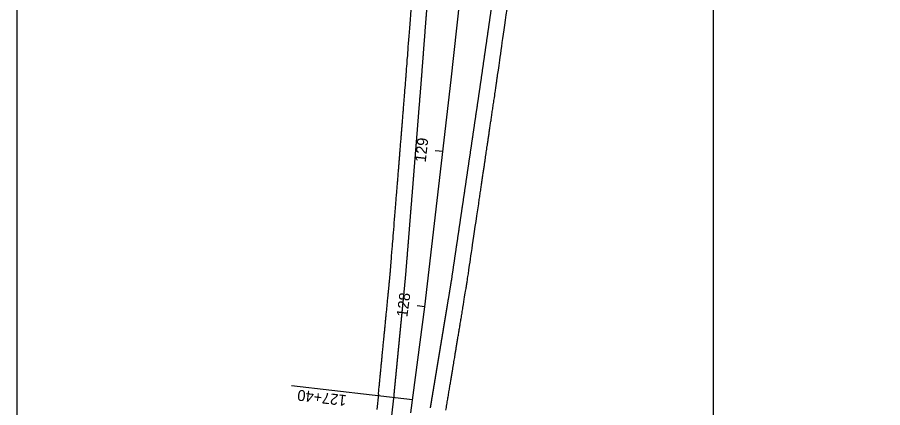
# Model space of a CAD drawing. Extents: x 2318076 to 2324211, y 613525 to 630327.
# Drawn here: x 2320224 to 2320778, y 627311 to 627561 of the extents above; entities that cross this region are included whole.
import ezdxf

# ---------------------------------------------------------------- set-up
doc = ezdxf.new("R2010")
doc.units = 0
for name, color, linetype in [('GE_P_CL_50', 7, 'Continuous'), ('PV_P_EOP', 7, 'Continuous'), ('PV_P_Shoulder', 7, 'Continuous'), ('SC_Scratch3', 7, 'Continuous')]:
    doc.layers.add(name, color=color, linetype=linetype)

msp = doc.modelspace()

# ---------------------------------------------------------------- linework, layer by layer
at = {"layer": 'GE_P_CL_50'}
for p, q in [((2320496.86, 627474.89), (2320491.9, 627475.45)), ((2320485.22, 627375.57), (2320480.26, 627376.22)), ((2320477.27, 627316.1), (2320399.9, 627325.01))]:
    msp.add_line(p, q, dxfattribs=at)
msp.add_lwpolyline([(2320476.3, 627307.7), (2320485.22, 627375.57), (2320502.11, 627520.92), (2320519.22, 627676.47), (2320531.82, 627783.89), (2320546.8, 627927.12), (2320554.45, 627991.34), (2320572.51, 628138.41), (2320649.52, 628804.84), (2320678.77, 629064.5), (2320690.76, 629163.78), (2320713.75, 629362.45), (2320725.26, 629461.78), (2320736.97, 629561.09), (2320748.4, 629660.43), (2320759.09, 629759.86), (2320769.62, 629859.3), (2320777.51, 629931.12), (2320778.25, 629937.84)], dxfattribs=at)
at = {"layer": 'PV_P_EOP'}
msp.add_lwpolyline([(2320449.32, 627178.38), (2320465.49, 627318.74)], dxfattribs=at)
for points in [[(2320482.44, 627513.23), (2320482.51, 627514.12), (2320482.59, 627515.02), (2320482.66, 627515.92), (2320482.73, 627516.82), (2320482.8, 627517.72), (2320482.88, 627518.62), (2320482.95, 627519.52), (2320483.02, 627520.41), (2320483.09, 627521.31), (2320483.16, 627522.21), (2320483.23, 627523.04), (2320483.3, 627523.94), (2320483.37, 627524.84), (2320483.43, 627525.73), (2320483.5, 627526.63), (2320483.57, 627527.53), (2320483.64, 627528.43), (2320483.71, 627529.33), (2320483.78, 627530.23), (2320483.85, 627531.13), (2320483.91, 627532.03), (2320483.98, 627532.92), (2320484.05, 627533.82), (2320484.12, 627534.72), (2320484.19, 627535.62), (2320484.26, 627536.52), (2320484.33, 627537.42), (2320484.4, 627538.32), (2320484.46, 627539.22), (2320484.53, 627540.11), (2320484.6, 627541.01), (2320484.67, 627541.91), (2320484.74, 627542.81), (2320484.81, 627543.71), (2320484.88, 627544.61), (2320484.94, 627545.51), (2320485.01, 627546.41), (2320485.08, 627547.31), (2320485.15, 627548.2), (2320485.22, 627549.1), (2320485.29, 627550), (2320485.36, 627550.9), (2320485.43, 627551.8), (2320485.49, 627552.7), (2320485.56, 627553.6), (2320485.63, 627554.5), (2320485.7, 627555.39), (2320485.77, 627556.29), (2320485.84, 627557.19), (2320485.91, 627558.09), (2320485.98, 627558.99), (2320486.04, 627559.89), (2320486.11, 627560.79), (2320486.18, 627561.69), (2320486.25, 627562.58), (2320486.32, 627563.48), (2320486.39, 627564.38), (2320486.46, 627565.28), (2320486.52, 627566.18), (2320486.59, 627567.08), (2320486.66, 627567.98), (2320486.73, 627568.88), (2320486.8, 627569.77), (2320486.87, 627570.67), (2320486.94, 627571.57), (2320487.01, 627572.47), (2320487.07, 627573.37), (2320487.14, 627574.27), (2320487.21, 627575.17), (2320487.28, 627576.07), (2320487.35, 627576.96), (2320487.42, 627577.86), (2320487.49, 627578.76), (2320487.56, 627579.66)], [(2320519.54, 627509), (2320519.67, 627509.89), (2320519.8, 627510.78), (2320519.93, 627511.68), (2320520.06, 627512.57), (2320520.2, 627513.46), (2320520.33, 627514.35), (2320520.46, 627515.24), (2320520.59, 627516.14), (2320520.72, 627517.03), (2320520.85, 627517.92), (2320520.99, 627518.88), (2320521.12, 627519.77), (2320521.25, 627520.67), (2320521.38, 627521.56), (2320521.51, 627522.45), (2320521.64, 627523.34), (2320521.76, 627524.24), (2320521.89, 627525.13), (2320522.02, 627526.02), (2320522.15, 627526.91), (2320522.28, 627527.8), (2320522.41, 627528.7), (2320522.53, 627529.59), (2320522.66, 627530.48), (2320522.79, 627531.37), (2320522.92, 627532.27), (2320523.05, 627533.16), (2320523.18, 627534.05), (2320523.3, 627534.94), (2320523.43, 627535.83), (2320523.56, 627536.73), (2320523.69, 627537.62), (2320523.82, 627538.51), (2320523.95, 627539.4), (2320524.08, 627540.3), (2320524.2, 627541.19), (2320524.33, 627542.08), (2320524.46, 627542.97), (2320524.59, 627543.86), (2320524.72, 627544.76), (2320524.85, 627545.65), (2320524.97, 627546.54), (2320525.1, 627547.43), (2320525.23, 627548.33), (2320525.36, 627549.22), (2320525.49, 627550.11), (2320525.62, 627551), (2320525.74, 627551.89), (2320525.87, 627552.79), (2320526, 627553.68), (2320526.13, 627554.57), (2320526.26, 627555.46), (2320526.39, 627556.36), (2320526.51, 627557.25), (2320526.64, 627558.14), (2320526.77, 627559.03), (2320526.9, 627559.92), (2320527.03, 627560.82), (2320527.16, 627561.71), (2320527.28, 627562.6), (2320527.41, 627563.49), (2320527.54, 627564.38), (2320527.67, 627565.28), (2320527.8, 627566.17), (2320527.93, 627567.06), (2320528.06, 627567.95), (2320528.18, 627568.85), (2320528.31, 627569.74), (2320528.44, 627570.63), (2320528.57, 627571.52), (2320528.7, 627572.41), (2320528.83, 627573.31), (2320528.95, 627574.2), (2320529.08, 627575.09)], [(2320477.11, 627446.74), (2320477.18, 627447.63), (2320477.25, 627448.53), (2320477.32, 627449.43), (2320477.39, 627450.33), (2320477.47, 627451.23), (2320477.54, 627452.13), (2320477.61, 627453.03), (2320477.68, 627453.92), (2320477.76, 627454.82), (2320477.83, 627455.72), (2320477.9, 627456.62), (2320477.97, 627457.52), (2320478.04, 627458.42), (2320478.12, 627459.32), (2320478.19, 627460.21), (2320478.26, 627461.11), (2320478.33, 627462.01), (2320478.4, 627462.91), (2320478.48, 627463.81), (2320478.55, 627464.71), (2320478.62, 627465.61), (2320478.69, 627466.5), (2320478.76, 627467.4), (2320478.84, 627468.3), (2320478.91, 627469.2), (2320478.98, 627470.1), (2320479.05, 627471), (2320479.13, 627471.89), (2320479.2, 627472.79), (2320479.27, 627473.69), (2320479.34, 627474.59), (2320479.41, 627475.49), (2320479.49, 627476.39), (2320479.56, 627477.29), (2320479.63, 627478.18), (2320479.7, 627479.08), (2320479.77, 627479.98), (2320479.85, 627480.88), (2320479.92, 627481.78), (2320479.99, 627482.68), (2320480.06, 627483.58), (2320480.13, 627484.47), (2320480.21, 627485.37), (2320480.28, 627486.27), (2320480.35, 627487.17), (2320480.42, 627488.07), (2320480.5, 627488.97), (2320480.57, 627489.87), (2320480.64, 627490.76), (2320480.71, 627491.66), (2320480.78, 627492.56), (2320480.86, 627493.46), (2320480.93, 627494.36), (2320481, 627495.26), (2320481.07, 627496.15), (2320481.14, 627497.05), (2320481.22, 627497.95), (2320481.29, 627498.85), (2320481.36, 627499.75), (2320481.43, 627500.65), (2320481.51, 627501.55), (2320481.58, 627502.44), (2320481.65, 627503.34), (2320481.72, 627504.24), (2320481.79, 627505.14), (2320481.87, 627506.04), (2320481.94, 627506.94), (2320482.01, 627507.84), (2320482.08, 627508.73), (2320482.15, 627509.63), (2320482.23, 627510.53), (2320482.3, 627511.43), (2320482.37, 627512.33), (2320482.44, 627513.23)], [(2320509.78, 627443.01), (2320509.92, 627443.91), (2320510.05, 627444.8), (2320510.18, 627445.69), (2320510.31, 627446.58), (2320510.44, 627447.47), (2320510.57, 627448.36), (2320510.71, 627449.26), (2320510.84, 627450.15), (2320510.97, 627451.04), (2320511.1, 627451.93), (2320511.23, 627452.82), (2320511.37, 627453.72), (2320511.5, 627454.61), (2320511.63, 627455.5), (2320511.76, 627456.39), (2320511.89, 627457.28), (2320512.02, 627458.17), (2320512.16, 627459.07), (2320512.29, 627459.96), (2320512.42, 627460.85), (2320512.55, 627461.74), (2320512.68, 627462.63), (2320512.81, 627463.52), (2320512.95, 627464.42), (2320513.08, 627465.31), (2320513.21, 627466.2), (2320513.34, 627467.09), (2320513.47, 627467.98), (2320513.61, 627468.87), (2320513.74, 627469.77), (2320513.87, 627470.66), (2320514, 627471.55), (2320514.13, 627472.44), (2320514.26, 627473.33), (2320514.4, 627474.22), (2320514.53, 627475.12), (2320514.66, 627476.01), (2320514.79, 627476.9), (2320514.92, 627477.79), (2320515.06, 627478.68), (2320515.19, 627479.57), (2320515.32, 627480.47), (2320515.45, 627481.36), (2320515.58, 627482.25), (2320515.71, 627483.14), (2320515.85, 627484.03), (2320515.98, 627484.93), (2320516.11, 627485.82), (2320516.24, 627486.71), (2320516.37, 627487.6), (2320516.5, 627488.49), (2320516.64, 627489.38), (2320516.77, 627490.28), (2320516.9, 627491.17), (2320517.03, 627492.06), (2320517.16, 627492.95), (2320517.3, 627493.84), (2320517.43, 627494.73), (2320517.56, 627495.63), (2320517.69, 627496.52), (2320517.82, 627497.41), (2320517.95, 627498.3), (2320518.09, 627499.19), (2320518.22, 627500.08), (2320518.35, 627500.98), (2320518.48, 627501.87), (2320518.61, 627502.76), (2320518.75, 627503.65), (2320518.88, 627504.54), (2320519.01, 627505.43), (2320519.14, 627506.33), (2320519.27, 627507.22), (2320519.4, 627508.11), (2320519.54, 627509)], [(2320471.53, 627380.52), (2320471.62, 627381.42), (2320471.7, 627382.32), (2320471.79, 627383.22), (2320471.88, 627384.11), (2320471.97, 627385.01), (2320472.05, 627385.91), (2320472.14, 627386.8), (2320472.23, 627387.7), (2320472.32, 627388.6), (2320472.4, 627389.5), (2320472.49, 627390.39), (2320472.58, 627391.29), (2320472.67, 627392.19), (2320472.75, 627393.08), (2320472.84, 627393.98), (2320472.93, 627394.88), (2320473.02, 627395.78), (2320473.07, 627396.42), (2320473.14, 627397.32), (2320473.21, 627398.22), (2320473.28, 627399.12), (2320473.36, 627400.01), (2320473.43, 627400.91), (2320473.5, 627401.81), (2320473.57, 627402.71), (2320473.64, 627403.61), (2320473.72, 627404.51), (2320473.79, 627405.4), (2320473.86, 627406.3), (2320473.93, 627407.2), (2320474.01, 627408.1), (2320474.08, 627409), (2320474.15, 627409.9), (2320474.22, 627410.8), (2320474.29, 627411.69), (2320474.37, 627412.59), (2320474.44, 627413.49), (2320474.51, 627414.39), (2320474.58, 627415.29), (2320474.65, 627416.19), (2320474.73, 627417.09), (2320474.8, 627417.98), (2320474.87, 627418.88), (2320474.94, 627419.78), (2320475.01, 627420.68), (2320475.09, 627421.58), (2320475.16, 627422.48), (2320475.23, 627423.38), (2320475.3, 627424.27), (2320475.38, 627425.17), (2320475.45, 627426.07), (2320475.52, 627426.97), (2320475.59, 627427.87), (2320475.66, 627428.77), (2320475.74, 627429.66), (2320475.81, 627430.56), (2320475.88, 627431.46), (2320475.95, 627432.36), (2320476.02, 627433.26), (2320476.1, 627434.16), (2320476.17, 627435.06), (2320476.24, 627435.95), (2320476.31, 627436.85), (2320476.38, 627437.75), (2320476.46, 627438.65), (2320476.53, 627439.55), (2320476.6, 627440.45), (2320476.67, 627441.35), (2320476.75, 627442.24), (2320476.82, 627443.14), (2320476.89, 627444.04), (2320476.96, 627444.94), (2320477.03, 627445.84), (2320477.11, 627446.74)], [(2320499.73, 627376.82), (2320499.88, 627377.71), (2320500.02, 627378.6), (2320500.17, 627379.48), (2320500.32, 627380.37), (2320500.47, 627381.26), (2320500.61, 627382.15), (2320500.76, 627383.04), (2320500.91, 627383.93), (2320501.05, 627384.82), (2320501.2, 627385.71), (2320501.35, 627386.6), (2320501.5, 627387.49), (2320501.64, 627388.38), (2320501.79, 627389.27), (2320501.94, 627390.16), (2320502.08, 627391.05), (2320502.23, 627391.93), (2320502.4, 627393.08), (2320502.54, 627393.97), (2320502.67, 627394.86), (2320502.8, 627395.75), (2320502.93, 627396.65), (2320503.06, 627397.54), (2320503.19, 627398.43), (2320503.33, 627399.32), (2320503.46, 627400.21), (2320503.59, 627401.1), (2320503.72, 627402), (2320503.85, 627402.89), (2320503.98, 627403.78), (2320504.12, 627404.67), (2320504.25, 627405.56), (2320504.38, 627406.45), (2320504.51, 627407.35), (2320504.64, 627408.24), (2320504.78, 627409.13), (2320504.91, 627410.02), (2320505.04, 627410.91), (2320505.17, 627411.8), (2320505.3, 627412.7), (2320505.43, 627413.59), (2320505.57, 627414.48), (2320505.7, 627415.37), (2320505.83, 627416.26), (2320505.96, 627417.15), (2320506.09, 627418.05), (2320506.23, 627418.94), (2320506.36, 627419.83), (2320506.49, 627420.72), (2320506.62, 627421.61), (2320506.75, 627422.51), (2320506.88, 627423.4), (2320507.02, 627424.29), (2320507.15, 627425.18), (2320507.28, 627426.07), (2320507.41, 627426.96), (2320507.54, 627427.86), (2320507.68, 627428.75), (2320507.81, 627429.64), (2320507.94, 627430.53), (2320508.07, 627431.42), (2320508.2, 627432.31), (2320508.33, 627433.21), (2320508.47, 627434.1), (2320508.6, 627434.99), (2320508.73, 627435.88), (2320508.86, 627436.77), (2320508.99, 627437.66), (2320509.12, 627438.56), (2320509.26, 627439.45), (2320509.39, 627440.34), (2320509.52, 627441.23), (2320509.65, 627442.12), (2320509.78, 627443.01)]]:
    msp.add_spline(points, degree=3, dxfattribs=at)
for points in [[(2320465.49, 627318.73), (2320465.52, 627318.99), (2320465.54, 627319.25), (2320465.57, 627319.52), (2320465.6, 627319.82), (2320465.63, 627320.12), (2320465.66, 627320.42), (2320465.69, 627320.72), (2320465.71, 627321.01), (2320465.74, 627321.31), (2320465.77, 627321.61), (2320465.8, 627321.91), (2320465.83, 627322.21), (2320465.86, 627322.51), (2320465.89, 627322.81), (2320465.92, 627323.11), (2320465.95, 627323.41), (2320465.98, 627323.71), (2320466.01, 627324), (2320466.04, 627324.3), (2320466.07, 627324.6), (2320466.09, 627324.9), (2320466.12, 627325.2), (2320466.15, 627325.5), (2320466.18, 627325.8), (2320466.21, 627326.1), (2320466.24, 627326.4), (2320466.27, 627326.7), (2320466.3, 627327), (2320466.33, 627327.29), (2320466.36, 627327.59), (2320466.39, 627327.89), (2320466.42, 627328.19), (2320466.45, 627328.49), (2320466.47, 627328.79), (2320466.5, 627329.09), (2320466.53, 627329.39), (2320466.56, 627329.69), (2320466.59, 627329.99), (2320466.62, 627330.28), (2320466.65, 627330.58), (2320466.68, 627330.88), (2320466.71, 627331.18), (2320466.74, 627331.48), (2320466.77, 627331.78), (2320466.8, 627332.08), (2320466.82, 627332.38), (2320466.85, 627332.68), (2320466.88, 627332.98), (2320466.91, 627333.28), (2320466.94, 627333.57), (2320466.97, 627333.87), (2320467, 627334.17), (2320467.03, 627334.47), (2320467.06, 627334.77), (2320467.09, 627335.07), (2320467.12, 627335.37), (2320467.15, 627335.67), (2320467.18, 627335.97), (2320467.2, 627336.27), (2320467.23, 627336.56), (2320467.26, 627336.86), (2320467.29, 627337.16), (2320467.32, 627337.46), (2320467.35, 627337.76), (2320467.38, 627338.06), (2320467.41, 627338.36), (2320467.44, 627338.66), (2320467.47, 627338.96), (2320467.5, 627339.26), (2320467.53, 627339.55), (2320467.56, 627339.85), (2320467.58, 627340.15), (2320467.61, 627340.45), (2320467.64, 627340.75), (2320467.67, 627341.05), (2320467.7, 627341.35), (2320467.73, 627341.65), (2320467.76, 627341.95), (2320467.79, 627342.25), (2320467.82, 627342.55), (2320467.85, 627342.84), (2320467.88, 627343.14), (2320467.91, 627343.44), (2320467.93, 627343.74), (2320467.96, 627344.04), (2320467.99, 627344.34), (2320468.02, 627344.64), (2320468.05, 627344.94), (2320468.08, 627345.24), (2320468.11, 627345.54), (2320468.14, 627345.83), (2320468.17, 627346.13), (2320468.2, 627346.43), (2320468.23, 627346.73), (2320468.26, 627347.03), (2320468.29, 627347.33), (2320468.31, 627347.63), (2320468.34, 627347.93), (2320468.37, 627348.23), (2320468.4, 627348.53), (2320468.43, 627348.83), (2320468.46, 627349.12), (2320468.49, 627349.42), (2320468.52, 627349.72), (2320468.55, 627350.02), (2320468.58, 627350.32), (2320468.61, 627350.62), (2320468.64, 627350.92), (2320468.67, 627351.22), (2320468.69, 627351.52), (2320468.72, 627351.82), (2320468.75, 627352.11), (2320468.78, 627352.41), (2320468.81, 627352.71), (2320468.84, 627353.01), (2320468.87, 627353.31), (2320468.9, 627353.61), (2320468.93, 627353.91), (2320468.96, 627354.21), (2320468.99, 627354.51), (2320469.02, 627354.81), (2320469.04, 627355.11), (2320469.07, 627355.4), (2320469.1, 627355.7), (2320469.13, 627356), (2320469.16, 627356.3), (2320469.19, 627356.6), (2320469.22, 627356.9), (2320469.25, 627357.2), (2320469.28, 627357.5), (2320469.31, 627357.8), (2320469.34, 627358.1), (2320469.37, 627358.39), (2320469.4, 627358.69), (2320469.42, 627358.99), (2320469.45, 627359.29), (2320469.48, 627359.59), (2320469.51, 627359.89), (2320469.54, 627360.19), (2320469.57, 627360.49), (2320469.6, 627360.79), (2320469.63, 627361.09), (2320469.66, 627361.39), (2320469.69, 627361.68), (2320469.72, 627361.98), (2320469.75, 627362.28), (2320469.78, 627362.58), (2320469.8, 627362.88), (2320469.83, 627363.18), (2320469.86, 627363.48), (2320469.89, 627363.78), (2320469.92, 627364.08), (2320469.95, 627364.38), (2320469.98, 627364.67), (2320470.01, 627364.97), (2320470.04, 627365.27), (2320470.07, 627365.57), (2320470.1, 627365.87), (2320470.13, 627366.17), (2320470.16, 627366.47), (2320470.18, 627366.77), (2320470.21, 627367.07), (2320470.24, 627367.37), (2320470.27, 627367.67), (2320470.3, 627367.96), (2320470.33, 627368.26), (2320470.36, 627368.56), (2320470.39, 627368.86), (2320470.42, 627369.16), (2320470.45, 627369.46), (2320470.48, 627369.76), (2320470.51, 627370.06), (2320470.53, 627370.36), (2320470.56, 627370.66), (2320470.59, 627370.95), (2320470.62, 627371.25), (2320470.65, 627371.55), (2320470.68, 627371.85), (2320470.71, 627372.15), (2320470.74, 627372.45), (2320470.77, 627372.75), (2320470.8, 627373.05), (2320470.83, 627373.35), (2320470.86, 627373.65), (2320470.89, 627373.94), (2320470.91, 627374.24), (2320470.94, 627374.54), (2320470.97, 627374.84), (2320471, 627375.14), (2320471.03, 627375.44), (2320471.06, 627375.74), (2320471.09, 627376.04), (2320471.12, 627376.34), (2320471.15, 627376.64), (2320471.18, 627376.94), (2320471.21, 627377.23), (2320471.24, 627377.53), (2320471.27, 627377.83), (2320471.29, 627378.13), (2320471.32, 627378.43), (2320471.35, 627378.73), (2320471.38, 627379.03), (2320471.41, 627379.33), (2320471.44, 627379.63), (2320471.47, 627379.93), (2320471.5, 627380.22), (2320471.53, 627380.52)], [(2320488.84, 627311.01), (2320488.89, 627311.3), (2320488.94, 627311.6), (2320488.99, 627311.9), (2320489.03, 627312.19), (2320489.08, 627312.49), (2320489.13, 627312.79), (2320489.18, 627313.08), (2320489.23, 627313.38), (2320489.28, 627313.68), (2320489.33, 627313.97), (2320489.38, 627314.27), (2320489.43, 627314.57), (2320489.48, 627314.86), (2320489.52, 627315.16), (2320489.57, 627315.45), (2320489.62, 627315.75), (2320489.67, 627316.05), (2320489.72, 627316.34), (2320489.77, 627316.64), (2320489.82, 627316.94), (2320489.87, 627317.23), (2320489.92, 627317.53), (2320489.97, 627317.83), (2320490.02, 627318.12), (2320490.06, 627318.42), (2320490.11, 627318.72), (2320490.16, 627319.01), (2320490.21, 627319.31), (2320490.26, 627319.6), (2320490.31, 627319.9), (2320490.36, 627320.2), (2320490.41, 627320.49), (2320490.46, 627320.79), (2320490.51, 627321.09), (2320490.56, 627321.38), (2320490.6, 627321.68), (2320490.65, 627321.98), (2320490.7, 627322.27), (2320490.75, 627322.57), (2320490.8, 627322.87), (2320490.85, 627323.16), (2320490.9, 627323.46), (2320490.95, 627323.76), (2320491, 627324.05), (2320491.05, 627324.35), (2320491.09, 627324.64), (2320491.14, 627324.94), (2320491.19, 627325.24), (2320491.24, 627325.53), (2320491.29, 627325.83), (2320491.34, 627326.13), (2320491.39, 627326.42), (2320491.44, 627326.72), (2320491.49, 627327.02), (2320491.54, 627327.31), (2320491.59, 627327.61), (2320491.63, 627327.91), (2320491.68, 627328.2), (2320491.73, 627328.5), (2320491.78, 627328.79), (2320491.83, 627329.09), (2320491.88, 627329.39), (2320491.93, 627329.68), (2320491.98, 627329.98), (2320492.03, 627330.28), (2320492.08, 627330.57), (2320492.13, 627330.87), (2320492.17, 627331.17), (2320492.22, 627331.46), (2320492.27, 627331.76), (2320492.32, 627332.06), (2320492.37, 627332.35), (2320492.42, 627332.65), (2320492.47, 627332.94), (2320492.52, 627333.24), (2320492.57, 627333.54), (2320492.62, 627333.83), (2320492.66, 627334.13), (2320492.71, 627334.43), (2320492.76, 627334.72), (2320492.81, 627335.02), (2320492.86, 627335.32), (2320492.91, 627335.61), (2320492.96, 627335.91), (2320493.01, 627336.21), (2320493.06, 627336.5), (2320493.11, 627336.8), (2320493.16, 627337.09), (2320493.2, 627337.39), (2320493.25, 627337.69), (2320493.3, 627337.98), (2320493.35, 627338.28), (2320493.4, 627338.58), (2320493.45, 627338.87), (2320493.5, 627339.17), (2320493.55, 627339.47), (2320493.6, 627339.76), (2320493.65, 627340.06), (2320493.7, 627340.36), (2320493.74, 627340.65), (2320493.79, 627340.95), (2320493.84, 627341.24), (2320493.89, 627341.54), (2320493.94, 627341.84), (2320493.99, 627342.13), (2320494.04, 627342.43), (2320494.09, 627342.73), (2320494.14, 627343.02), (2320494.19, 627343.32), (2320494.23, 627343.62), (2320494.28, 627343.91), (2320494.33, 627344.21), (2320494.38, 627344.51), (2320494.43, 627344.8), (2320494.48, 627345.1), (2320494.53, 627345.39), (2320494.58, 627345.69), (2320494.63, 627345.99), (2320494.68, 627346.28), (2320494.73, 627346.58), (2320494.77, 627346.88), (2320494.82, 627347.17), (2320494.87, 627347.47), (2320494.92, 627347.77), (2320494.97, 627348.06), (2320495.02, 627348.36), (2320495.07, 627348.66), (2320495.12, 627348.95), (2320495.17, 627349.25), (2320495.22, 627349.54), (2320495.27, 627349.84), (2320495.31, 627350.14), (2320495.36, 627350.43), (2320495.41, 627350.73), (2320495.46, 627351.03), (2320495.51, 627351.32), (2320495.56, 627351.62), (2320495.61, 627351.92), (2320495.66, 627352.21), (2320495.71, 627352.51), (2320495.76, 627352.81), (2320495.8, 627353.1), (2320495.85, 627353.4), (2320495.9, 627353.69), (2320495.95, 627353.99), (2320496, 627354.29), (2320496.05, 627354.58), (2320496.1, 627354.88), (2320496.15, 627355.18), (2320496.2, 627355.47), (2320496.25, 627355.77), (2320496.3, 627356.07), (2320496.34, 627356.36), (2320496.39, 627356.66), (2320496.44, 627356.96), (2320496.49, 627357.25), (2320496.54, 627357.55), (2320496.59, 627357.85), (2320496.64, 627358.14), (2320496.69, 627358.44), (2320496.74, 627358.73), (2320496.79, 627359.03), (2320496.84, 627359.33), (2320496.88, 627359.62), (2320496.93, 627359.92), (2320496.98, 627360.22), (2320497.03, 627360.51), (2320497.08, 627360.81), (2320497.13, 627361.11), (2320497.18, 627361.4), (2320497.23, 627361.7), (2320497.28, 627362), (2320497.33, 627362.29), (2320497.37, 627362.59), (2320497.42, 627362.88), (2320497.47, 627363.18), (2320497.52, 627363.48), (2320497.57, 627363.77), (2320497.62, 627364.07), (2320497.67, 627364.37), (2320497.72, 627364.66), (2320497.77, 627364.96), (2320497.82, 627365.26), (2320497.87, 627365.55), (2320497.91, 627365.85), (2320497.96, 627366.15), (2320498.01, 627366.44), (2320498.06, 627366.74), (2320498.11, 627367.03), (2320498.16, 627367.33), (2320498.21, 627367.63), (2320498.26, 627367.92), (2320498.31, 627368.22), (2320498.36, 627368.52), (2320498.41, 627368.81), (2320498.45, 627369.11), (2320498.5, 627369.41), (2320498.55, 627369.7), (2320498.6, 627370), (2320498.65, 627370.3), (2320498.7, 627370.59), (2320498.75, 627370.89), (2320498.8, 627371.18), (2320498.85, 627371.48), (2320498.9, 627371.78), (2320498.94, 627372.07), (2320498.99, 627372.37), (2320499.04, 627372.67), (2320499.09, 627372.96), (2320499.14, 627373.26), (2320499.19, 627373.56), (2320499.24, 627373.85), (2320499.29, 627374.15), (2320499.34, 627374.45), (2320499.39, 627374.74), (2320499.44, 627375.04), (2320499.48, 627375.33), (2320499.53, 627375.63), (2320499.58, 627375.93), (2320499.63, 627376.22), (2320499.68, 627376.52), (2320499.73, 627376.82)]]:
    msp.add_open_spline(points, degree=3, dxfattribs=at)
at = {"layer": 'PV_P_Shoulder'}
msp.add_line((2320455.54, 627319.7), (2320454.39, 627309.76), dxfattribs=at)
for points, degree in [([(2320472.47, 627514.03), (2320472.7, 627516.81), (2320472.93, 627519.57), (2320473.17, 627522.65), (2320473.2, 627523.08), (2320473.23, 627523.51), (2320473.25, 627523.68), (2320473.25, 627523.76), (2320473.27, 627524.02), (2320473.34, 627524.89), (2320473.51, 627527.13), (2320474.09, 627534.75), (2320475.47, 627552.74), (2320476.74, 627569.35), (2320477.58, 627580.42)], 3), ([(2320529.43, 627507.54), (2320529.83, 627510.28), (2320530.25, 627513.03), (2320530.7, 627516.16), (2320530.78, 627516.68), (2320530.86, 627517.21), (2320530.91, 627517.56), (2320530.93, 627517.73), (2320531.05, 627518.59), (2320531.35, 627520.65), (2320532.44, 627528.23), (2320535.02, 627546.13), (2320537.4, 627562.65), (2320538.98, 627573.67)], 3), ([(2320467.14, 627447.54), (2320468.92, 627469.7), (2320470.7, 627491.86), (2320472.47, 627514.03)], 2), ([(2320519.68, 627441.55), (2320522.93, 627463.55), (2320526.18, 627485.54), (2320529.43, 627507.54)], 2), ([(2320463.06, 627396.73), (2320463.07, 627396.76), (2320463.07, 627396.87), (2320463.09, 627397.1), (2320463.09, 627397.14), (2320463.1, 627397.19), (2320463.1, 627397.21), (2320463.1, 627397.22), (2320463.1, 627397.22), (2320463.1, 627397.22), (2320463.1, 627397.23), (2320463.1, 627397.26), (2320463.11, 627397.37), (2320463.14, 627397.73), (2320463.21, 627398.59), (2320463.36, 627400.44), (2320463.66, 627404.15), (2320464.25, 627411.56), (2320465.44, 627426.37), (2320466.46, 627439.07), (2320467.14, 627447.54)], 3), ([(2320509.6, 627375.18), (2320510.05, 627377.94), (2320510.73, 627382.07), (2320511.53, 627386.88), (2320511.9, 627389.12), (2320512.05, 627390.02), (2320512.09, 627390.24), (2320512.1, 627390.29), (2320512.1, 627390.3), (2320512.1, 627390.3), (2320512.1, 627390.31), (2320512.1, 627390.33), (2320512.11, 627390.38), (2320512.14, 627390.55), (2320512.16, 627390.7), (2320512.21, 627391.03), (2320512.24, 627391.22), (2320512.27, 627391.47), (2320512.29, 627391.55), (2320512.3, 627391.62), (2320512.3, 627391.63), (2320512.3, 627391.64), (2320512.3, 627391.65), (2320512.31, 627391.69), (2320512.32, 627391.77), (2320513.14, 627397.35), (2320515.6, 627413.95), (2320518.04, 627430.51), (2320519.68, 627441.55)], 3), ([(2320461.58, 627381.5), (2320462.07, 627386.58), (2320462.57, 627391.65), (2320463.06, 627396.73)], 2), ([(2320455.54, 627319.7), (2320457.55, 627340.3), (2320459.56, 627360.9), (2320461.58, 627381.5)], 2), ([(2320498.7, 627309.38), (2320502.33, 627331.31), (2320505.97, 627353.25), (2320509.6, 627375.18)], 2)]:
    msp.add_open_spline(points, degree=degree, dxfattribs=at)
at = {"layer": 'SC_Scratch3'}
for p, q in [((2320224.38, 614778.41), (2320224.38, 630327.22)), ((2320669.87, 614778.41), (2320669.87, 630327.22))]:
    msp.add_line(p, q, dxfattribs=at)

# ---------------------------------------------------------------- texts
at = {"layer": 'GE_P_CL_50'}
for s, rotation, p in [('129', 83.502, (2320485.74, 627467.8)), ('128', 82.5115, (2320473.97, 627368.64)), ('127+40', 173.4266, (2320435.38, 627318.96))]:
    msp.add_text(s, height=7, rotation=rotation, dxfattribs=at).set_placement(p)

doc.saveas('drawing.dxf')
